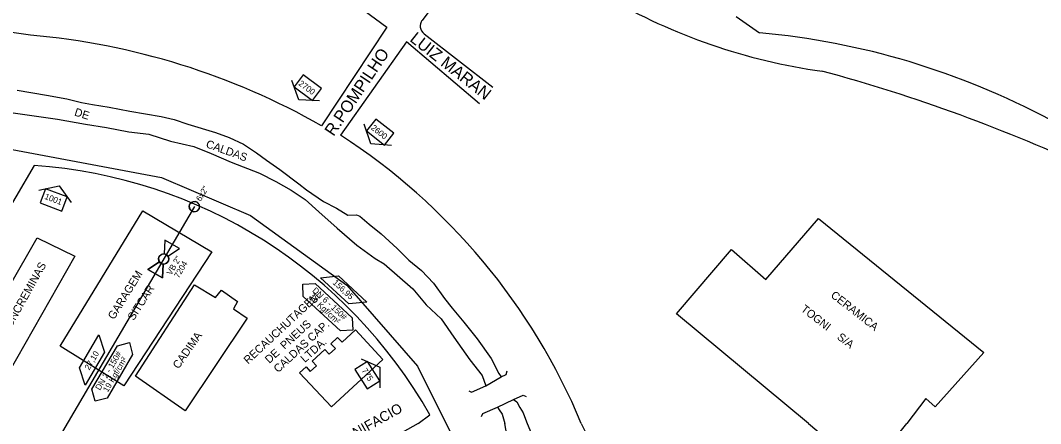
# Model space of a CAD drawing. Extents: x 325709 to 364434, y 7573432 to 7597073.
# Drawn here: x 334613 to 335123, y 7590502 to 7590704 of the extents above; entities that cross this region are included whole.
import ezdxf

# ---------------------------------------------------------------- set-up
doc = ezdxf.new("R2010")
doc.units = 0
for name, color, linetype in [('EDIFEXISTENT', 7, 'Continuous'), ('EDIFIDENTIF', 7, 'Continuous'), ('EDIFOBRAEXIS', 7, 'Continuous'), ('FORMATO', 7, 'Continuous'), ('LOGRADOURO', 7, 'Continuous'), ('LOGRADOURO_TEXTO', 7, 'Continuous'), ('NUM_REF', 7, 'Continuous'), ('SIMBOLO', 7, 'Continuous'), ('TEXTO', 7, 'Continuous'), ('TUBO_ACO_GN_2', 7, 'Continuous'), ('TUBO_ACO_GN_6', 7, 'Continuous'), ('VALVULA_ACO_2', 7, 'Continuous')]:
    doc.layers.add(name, color=color, linetype=linetype)

# ---------------------------------------------------------------- blocks, each defined once
blk = doc.blocks.new('VALVULA_ACO_2')
at = {"layer": 'VALVULA_ACO_2'}
for points in [[(-1.14, 0.57), (-4.25, 2.13), (-4.25, -2.13), (-1.14, -0.57)], [(-1.14, -0.57), (-4.25, -2.13), (-4.25, 2.13), (-1.14, 0.57)], [(1.14, -0.57), (4.25, -2.13), (4.25, 2.13), (1.14, 0.57)], [(1.14, -0.57), (4.25, -2.13), (4.25, 2.13), (1.14, 0.57)]]:
    blk.add_lwpolyline(points, dxfattribs=at)
blk.add_circle((0, 0), 1.28, dxfattribs=at)
for start, end in [(90, 270), (153.4349, 206.5651), (270, 90), (0, 26.5651), (333.4349, 0)]:
    blk.add_arc((0, 0), 1.28, start, end, dxfattribs=at)
blk = doc.blocks.new('INTERLIGACAO')
at = {"layer": 'SIMBOLO'}
blk.add_circle((0, 0), 1.28, dxfattribs=at)
for start, end in [(0, 180), (180, 0)]:
    blk.add_arc((0, 0), 1.28, start, end, dxfattribs=at)
blk = doc.blocks.new('NUM_REF')
at = {"layer": 'NUM_REF'}
blk.add_lwpolyline([(-4.3125, 0.9375), (0, 3.75), (4.3125, 0.9375)], dxfattribs=at)
blk.add_lwpolyline([(2.875, -1.875), (2.875, 1.875), (-2.875, 1.875), (-2.875, -1.875)], close=True, dxfattribs=at)

msp = doc.modelspace()

# ---------------------------------------------------------------- linework, layer by layer
at = {"layer": 'EDIFEXISTENT'}
for p, q in [((334633.23, 7590540.67), (334674.6, 7590608.27)), ((334794.45, 7590533.92), (334768.78, 7590510.25)), ((334695.77, 7590508.37), (334670.91, 7590525.66)), ((334768.78, 7590510.25), (334752.89, 7590527.28))]:
    msp.add_line(p, q, dxfattribs=at)
for points in [[(334674.6, 7590608.27), (334709.05, 7590587.76), (334665.07, 7590520.77), (334633.23, 7590540.67)], [(335007.21, 7590501.91), (334941.33, 7590556.89), (334968.82, 7590588.94), (334985.9, 7590574.03), (335012.18, 7590604.43), (335094.84, 7590537.54), (335070.57, 7590510.36), (335065.86, 7590514.42), (335056.42, 7590501.91)], [(334580, 7590522.34), (334621.71, 7590594.78), (334640.48, 7590585.63), (334598.78, 7590512.32)], [(334670.91, 7590525.66), (334700.4, 7590571.33), (334710.89, 7590564.98), (334713.84, 7590568.61), (334721.87, 7590563.07), (334719.8, 7590559.24), (334726.75, 7590554.72), (334695.77, 7590508.37)], [(334752.89, 7590527.28), (334756.11, 7590530.35), (334758.25, 7590527.99), (334761.36, 7590530.84), (334759.18, 7590533.21), (334765.55, 7590539.01), (334767.7, 7590536.65), (334770.78, 7590539.51), (334768.56, 7590541.87), (334771.91, 7590544.94), (334774.21, 7590542.58), (334780.87, 7590548.74), (334794.45, 7590533.92)], [(334837.4, 7590518.24), (334838.82, 7590517.66), (334845.95, 7590520.88), (334853.59, 7590525.36), (334856.13, 7590526.47), (334856.66, 7590528.37)], [(334843.76, 7590505.48), (334844.52, 7590507.03), (334851.73, 7590510.12), (334859.87, 7590513.96), (334864.69, 7590516.07), (334866.19, 7590515.48)], [(335007.21, 7590501.91), (335036.61, 7590477.29), (335056.42, 7590501.91)]]:
    msp.add_lwpolyline(points, dxfattribs=at)
at = {"layer": 'EDIFOBRAEXIS'}
for points in [[(334611.8, 7590668.67), (334626.43, 7590666.22), (334636.47, 7590664.33), (334643.85, 7590662.58), (334649.35, 7590661.51), (334657.7, 7590660.23), (334667.99, 7590658.19), (334683.72, 7590655.49), (334690.13, 7590654.01), (334697.03, 7590651.68), (334710.85, 7590647.55), (334717.72, 7590645.04), (334724.87, 7590641.71), (334731.41, 7590637.39), (334736.28, 7590633.76), (334743.04, 7590629.04), (334752.52, 7590621.88), (334756.38, 7590618.8), (334764.79, 7590612.99), (334771.33, 7590609.74), (334777.01, 7590606.13), (334781.37, 7590606.41), (334782.92, 7590605.72), (334787.61, 7590601.71), (334793.69, 7590596.78), (334801.73, 7590589.5), (334807.43, 7590583.71), (334813.76, 7590578.43), (334819.8, 7590572.11), (334825.37, 7590564.57), (334829.12, 7590559.62), (334835.02, 7590552.61), (334841.66, 7590544.29), (334848.7, 7590534.54), (334852.55, 7590527.01), (334853.59, 7590525.36)], [(334609.78, 7590657.3), (334631.87, 7590654.24), (334645.95, 7590651.64), (334656.37, 7590650.04), (334667.5, 7590647.87), (334677.47, 7590646.72), (334688.37, 7590643.21), (334699.99, 7590640.56), (334708.66, 7590636.98), (334718.62, 7590632.74), (334732.92, 7590627.25), (334740.98, 7590623.03), (334748.74, 7590618.71), (334755.61, 7590613.99), (334762.45, 7590607.79), (334771.68, 7590599.72), (334781.51, 7590591.09), (334790.64, 7590584.43), (334795.12, 7590581.79), (334809.55, 7590569.33), (334816.18, 7590561.36), (334823.64, 7590554.4), (334830.04, 7590545.16), (334837.9, 7590533.79), (334844.13, 7590525.98), (334845.95, 7590520.88)], [(334859.87, 7590513.96), (334861.47, 7590512.82), (334862.94, 7590509.98), (334864.56, 7590507.32), (334865.27, 7590505.46), (334866.58, 7590501.91)], [(334851.73, 7590510.12), (334852.71, 7590508.77), (334854.07, 7590506.63), (334855.52, 7590501.91)], [(334857.02, 7590493.5), (334855.52, 7590501.91)], [(334866.58, 7590501.91), (334878.4, 7590473.83)]]:
    msp.add_lwpolyline(points, dxfattribs=at)
at = {"layer": 'LOGRADOURO'}
for p, q in [((334846.44, 7590746.85), (334814.07, 7590703.59)), ((334756.24, 7590730.12), (334796.54, 7590700.17)), ((334618.41, 7590696.14), (334585.58, 7590700.73)), ((334971.06, 7590705.58), (334982.81, 7590697.41)), ((334796.54, 7590700.17), (334763.82, 7590650.88)), ((334815.12, 7590696.93), (334849.45, 7590670.12)), ((334806.31, 7590692.87), (334773.28, 7590646.19)), ((334842.89, 7590661.78), (334806.31, 7590692.87)), ((334620.15, 7590630.96), (334544.54, 7590501.91)), ((334812.09, 7590501.91), (334818.04, 7590506.27)), ((334893.69, 7590501.91), (334974.89, 7590339.21))]:
    msp.add_line(p, q, dxfattribs=at)
msp.add_lwpolyline([(334812.09, 7590501.91), (334781.04, 7590484.38), (334771.85, 7590479.69), (334742.6, 7590462.23)], dxfattribs=at)
for centre, radius, start, end in [((335054.14, 7590968.71), 293.26, 239.7994, 262.1319), ((334818.04, 7590700.8), 4.86, 144.8846, 188.0649), ((334588.22, 7590342.93), 354.5, 60.3081, 85.1154), ((334818.46, 7590701.07), 5.31, 190.2608, 231.1034), ((334947.77, 7590316.33), 382.69, 61.929, 84.7456), ((334794.4, 7589867.28), 840.14, 64.97342, 74.84819), ((334601.63, 7590380.54), 316.28, 22.5659, 57.1315), ((334603.54, 7590385.24), 246.29, 29.4333, 86.1333)]:
    msp.add_arc(centre, radius, start, end, dxfattribs=at)
at = {"layer": 'SIMBOLO'}
for points in [[(334777.5, 7590561.83), (334763.38, 7590574.88), (334772.37, 7590575.76), (334786.48, 7590562.72)], [(334655.38, 7590537.73), (334645.66, 7590521.14), (334642.87, 7590529.73), (334652.59, 7590546.31)]]:
    msp.add_lwpolyline(points, close=True, dxfattribs=at)
for points in [[(334754.47, 7590571.71), (334760.66, 7590571.95), (334779.2, 7590554.81), (334779.45, 7590548.63), (334773.26, 7590548.39), (334754.72, 7590565.52), (334754.47, 7590571.71)], [(334650.67, 7590513.12), (334649.11, 7590519.11), (334661.87, 7590540.89), (334667.86, 7590542.46), (334669.42, 7590536.47), (334656.66, 7590514.68), (334650.67, 7590513.12)]]:
    msp.add_lwpolyline(points, dxfattribs=at)
at = {"layer": 'TUBO_ACO_GN_2'}
msp.add_line((334700.3, 7590610.44), (334625.36, 7590482.53), dxfattribs=at)
at = {"layer": 'TUBO_ACO_GN_6'}
msp.add_lwpolyline([(334470.2, 7590681.15), (334482.35, 7590673), (334542.78, 7590651.23), (334609.3, 7590639.02), (334683.95, 7590625.06), (334728.27, 7590606.02), (334776.5, 7590571.23), (334811.79, 7590530.63), (334860.49, 7590433.14), (334895.26, 7590364.22), (334935.45, 7590301.18), (334990.33, 7590244.85), (335022.54, 7590222.2), (335129.5, 7590177.7), (335139.99, 7590175.87), (335552.51, 7590149.25), (335567.38, 7590148.97), (335781.87, 7590140.07)], dxfattribs=at)

# ---------------------------------------------------------------- block references
at = {"layer": 'FORMATO'}
for p, xscale, yscale, rotation in [((334757.02, 7590669.94), 1.9999999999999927, 1.9999999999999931, 143.3856237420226), ((334793.18, 7590647.76), 1.9999999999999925, 1.9999999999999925, 141.8733667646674), ((334630, 7590613.81), 1.9999999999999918, 1.9999999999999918, -20.908066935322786), ((334786.7, 7590526.12), 1.9999999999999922, 1.9999999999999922, -57.319002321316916)]:
    msp.add_blockref('NUM_REF', p, dxfattribs=dict(at, xscale=xscale, yscale=yscale, rotation=rotation))
at = {"layer": 'SIMBOLO', "xscale": 1.9999999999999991, "yscale": 1.9999999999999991, "rotation": 59.056983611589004}
msp.add_blockref('INTERLIGACAO', (334700.3, 7590610.44), dxfattribs=at)
at = {"layer": 'VALVULA_ACO_2', "xscale": 1.9999999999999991, "yscale": 1.9999999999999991, "rotation": 59.634752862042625}
msp.add_blockref('VALVULA_ACO_2', (334684.95, 7590584.25), dxfattribs=at)

# ---------------------------------------------------------------- texts
for s, rotation, p in [('2700', 323.3856, (334752.07, 7590671.43)), ('2600', 321.8734, (334788.27, 7590649.37)), ('6x2"', 59.057, (334703.47, 7590612.81)), ('1001', 339.0919, (334625.17, 7590614.37)), ('VB 2"', 59.6348, (334688.75, 7590575.89)), ('7204', 59.6348, (334692.52, 7590574.41)), ('775', 302.681, (334783.77, 7590528.46))]:
    msp.add_text(s, height=3, rotation=rotation).set_placement(p)
at = {"layer": 'EDIFIDENTIF'}
for s, rotation, p in [('DE', 342.533, (334640.02, 7590656.08)), ('CALDAS', 340.0991, (334705.74, 7590640.22)), ('CONCREMINAS', 60.8584, (334606.89, 7590546.21)), ('GARAGEM', 58.0532, (334660.14, 7590553.63)), ('SITCAR', 57.3693, (334669.97, 7590553.16)), ('RECAUCHUTAGEM', 42.9265, (334727.13, 7590531.45)), ('CERAMICA', 321.9048, (335018.01, 7590565.49)), ('TOGNI    S/A', 322.2835, (335003.11, 7590558.51)), ('DE  PNEUS', 42.46, (334737.75, 7590531.76)), ('CALDAS CAP.', 42.5465, (334742.14, 7590527.12)), ('CADIMA', 54.9692, (334692.41, 7590528.97)), ('LTDA.', 41.8322, (334755.52, 7590532.18))]:
    msp.add_text(s, height=4, rotation=rotation, dxfattribs=at).set_placement(p)
at = {"layer": 'LOGRADOURO_TEXTO'}
for s, height, rotation, p in [('LUIZ MARAN', 6, 321.6504, (334807.55, 7590693.54)), ('R.POMPILHO', 6, 56.1346, (334769.92, 7590645.26)), ('BONIFACIO', 5, 29.4139, (334772.77, 7590490.04))]:
    msp.add_text(s, height=height, rotation=rotation, dxfattribs=at).set_placement(p)
at = {"layer": 'TEXTO'}
for s, rotation, p in [('156,95', 317.2619, (334769.21, 7590572.04)), ('DN 6 - 150#', 317.2619, (334759, 7590568.2)), ('19 Kgf/cm²', 317.2619, (334757.28, 7590564.62)), ('27,10', 59.6348, (334647.77, 7590528.45)), ('DN 2 - 150#', 59.6348, (334653.12, 7590518.3)), ('19 Kgf/cm²', 59.6348, (334656.99, 7590517.38))]:
    msp.add_text(s, height=3, rotation=rotation, dxfattribs=at).set_placement(p)

doc.saveas('drawing.dxf')
